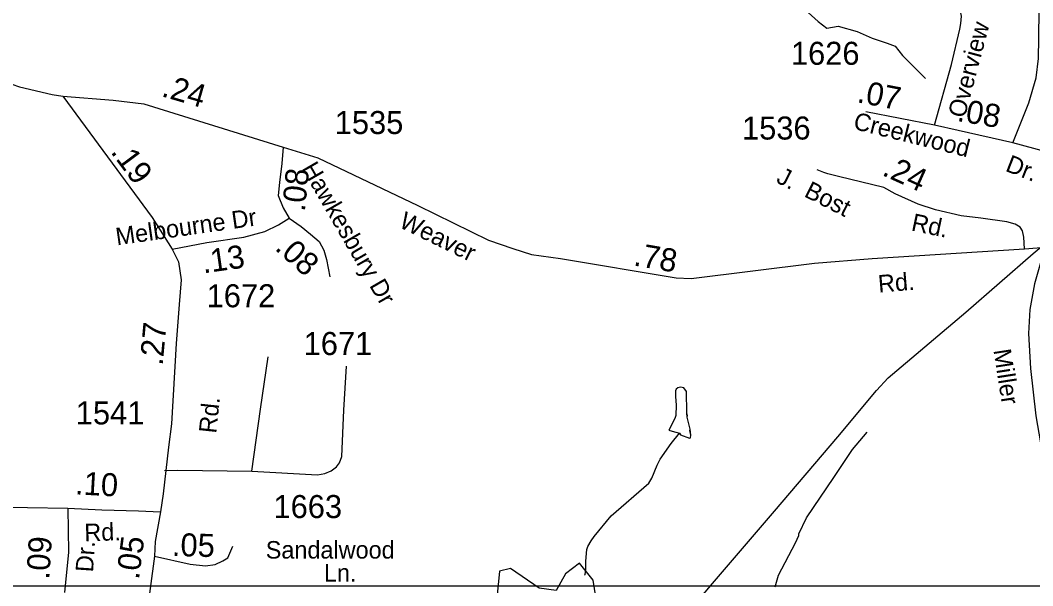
# Model space of a CAD drawing. Extents: x 1473865 to 1648260, y 639067 to 773536.
# Drawn here: x 1520569 to 1526062, y 678674 to 681743 of the extents above; entities that cross this region are included whole.
import ezdxf

# ---------------------------------------------------------------- set-up
doc = ezdxf.new("R2010")
doc.units = 0
for name, color, linetype in [('Exist Hydrographic Creek Single Shore', 7, 'Continuous'), ('Exist Hydrographic Misc Water Feature', 7, 'Continuous'), ('Exist Hydrographic Pond Under 1500 Sq Ft', 7, 'Continuous'), ('Exist Road Non-System Type 51', 7, 'Continuous'), ('Exist Road Secondary Mileage Hundredths English Label', 7, 'Continuous'), ('Exist Road Secondary Type 41 Attributed', 7, 'Continuous'), ('Exist Road Secondary Type 51 Attributed', 7, 'Continuous'), ('Exist Road Secondary Type 51 Label', 7, 'Continuous'), ('Exist Road Secondary Type 51 Number Label', 7, 'Continuous'), ('Exist Utilities Electrical Transmission Line', 7, 'Continuous'), ('Map Preparation Inset Cut Line', 7, 'Continuous')]:
    doc.layers.add(name, color=color, linetype=linetype)

msp = doc.modelspace()

# ---------------------------------------------------------------- linework, layer by layer
at = {"layer": 'Exist Hydrographic Creek Single Shore'}
msp.add_lwpolyline([(1524806.7, 681817.8), (1524897.3, 681736.4), (1524944.8, 681699.3), (1525006.6, 681709.8), (1525109, 681681.6), (1525190.1, 681645.1), (1525271.3, 681619.2), (1525316, 681602.7), (1525354.9, 681551), (1525480.7, 681426.7)], dxfattribs=at)
at = {"layer": 'Exist Hydrographic Misc Water Feature'}
for points in [[(1524145.9, 679501.4), (1524151.6, 679493.1), (1524199.5, 679474.1), (1524205.4, 679476.4), (1524207.6, 679492), (1524202, 679516.7), (1524204.2, 679524), (1524187.2, 679588.4), (1524189.2, 679596.5), (1524185.7, 679612.2), (1524183.5, 679728.8), (1524169.8, 679748.7), (1524151.7, 679751.6), (1524135.6, 679747.8), (1524127.5, 679741.4), (1524123.4, 679731.6), (1524123, 679701.3), (1524128.2, 679653.6), (1524125.3, 679597.8), (1524121, 679581.5), (1524088.2, 679518.2), (1524105.9, 679512.1), (1524145.9, 679501.4)], [(1524145.9, 679501.4), (1524151.6, 679493.1), (1524199.5, 679474.1), (1524205.4, 679476.4), (1524207.6, 679492), (1524204.2, 679524), (1524187.2, 679588.4), (1524185.7, 679612.2), (1524183.5, 679728.8), (1524169.8, 679748.7), (1524151.7, 679751.6), (1524135.6, 679747.8), (1524127.5, 679741.4), (1524123.4, 679731.6), (1524123, 679701.3), (1524128.2, 679653.6), (1524125.3, 679597.8), (1524121, 679581.5), (1524088.2, 679518.2), (1524105.9, 679512.1), (1524145.9, 679501.4)], [(1523629.6, 678730.6), (1523633.5, 678734.6), (1523637.9, 678759.2), (1523636.6, 678806.8), (1523643.6, 678870.6), (1523647.8, 678887), (1523666.4, 678918.6), (1523682.8, 678942.1), (1523774.5, 679052.6), (1523979.6, 679229.8), (1523995.9, 679257.4), (1524025, 679329), (1524041.5, 679360.7), (1524100.9, 679445.7), (1524145.9, 679501.4)], [(1524664.9, 678668.7), (1524682, 678732.3), (1524774.8, 678906.9), (1524793.4, 678946.7), (1524793.3, 678954.9), (1524835, 679041.9), (1524982.4, 679262.1), (1525084.9, 679412.7), (1525164.4, 679507.1)]]:
    msp.add_lwpolyline(points, dxfattribs=at)
at = {"layer": 'Exist Hydrographic Pond Under 1500 Sq Ft'}
msp.add_lwpolyline([(1523727.2, 678203.4), (1523779.1, 678300.9), (1523781.2, 678402.6), (1523707.2, 678512.4), (1523677.1, 678703.4), (1523603.1, 678796.8), (1523527.1, 678739.2), (1523476.2, 678648.4), (1523384.1, 678660.1), (1523228.2, 678768.2), (1523169.1, 678753.1), (1523150.1, 678569.6), (1523065.2, 678512.2), (1523056.1, 678463.2), (1523105.1, 678412.9), (1523379.2, 678299.1), (1523493.1, 678155.6), (1523559.1, 678121.5), (1523727.2, 678203.4)], dxfattribs=at)
at = {"layer": 'Exist Road Non-System Type 51'}
for points in [[(1521825.3, 679296), (1521872.6, 679631.6), (1521914.8, 679916.7)], [(1521825.3, 679296), (1522182.3, 679276.4), (1522221.4, 679282.6), (1522256.4, 679297), (1522285.2, 679319.6), (1522301.7, 679340.2), (1522314, 679375.2), (1522324.3, 679626.4), (1522338.7, 679865.2)], [(1521352, 679300.1), (1521424, 679302.1), (1521825.3, 679296)]]:
    msp.add_lwpolyline(points, dxfattribs=at)
at = {"layer": 'Exist Road Secondary Type 41 Attributed'}
msp.add_lwpolyline([(1526017.3, 680502.5), (1526013.8, 680564.9), (1526006.8, 680600.2), (1525993.8, 680619), (1525965.6, 680636.7), (1525920.9, 680649.6), (1525780.3, 680669.2), (1525673.4, 680681.8), (1525535.1, 680713.3), (1525440.8, 680744.7), (1525315.1, 680801.4), (1525254.9, 680835.5), (1525008.9, 680894.4), (1524950.1, 680908.5), (1524928.9, 680916.7), (1524891.9, 680931.2)], dxfattribs=at)
at = {"layer": 'Exist Road Secondary Type 51 Attributed'}
for p, q in [((1525528.2, 681173.3), (1525157.2, 681245.8)), ((1526017.3, 680502.5), (1526130.3, 680512))]:
    msp.add_line(p, q, dxfattribs=at)
for points in [[(1525953.8, 681077.9), (1526040.9, 681294.4), (1526079.7, 681429.8), (1526092.7, 681534.5), (1526095, 681645.1), (1526097.4, 681799.2), (1526083.2, 681939.3), (1526071.5, 682034.6), (1526058.5, 682108.7), (1526065.6, 682175.8), (1526095, 682432.3), (1526100.9, 682637), (1526100.9, 682706.5), (1526087.9, 682758.2), (1526062.1, 682807.7), (1526023.2, 682846.5), (1525991.5, 682878.3), (1525921.7, 682908.8), (1525870.2, 682922.6), (1525731.6, 682938.3), (1525558.4, 682921.4)], [(1525528.2, 681173.3), (1525620.5, 681502.2), (1525666.7, 681694.4), (1525672.6, 681726), (1525674.5, 681764.8), (1525667.9, 681801.6), (1525644.3, 681847.5), (1525614.9, 681881.6), (1525556.1, 681920.4), (1525455.9, 681954.8), (1525250.2, 682045.2), (1525186.6, 682081.6), (1525138.4, 682126.4), (1525117.2, 682173.4), (1525109, 682212.3), (1525099.5, 682400.5), (1525101, 682801.3)], [(1518591.3, 682427), (1518787.2, 682221.1), (1519092.2, 681892.2), (1519158, 681835.4), (1519202.8, 681805.4), (1519334.4, 681745.6), (1519695.9, 681629.7), (1519970.1, 681544.3), (1520314, 681467.5), (1520565.4, 681381.4), (1520741.5, 681339), (1520799.5, 681331.1)], [(1520799.5, 681331.1), (1521072.4, 681309.8), (1521239.9, 681289), (1521996.2, 681054)], [(1520799.5, 681331.1), (1521285.4, 680673.2), (1521393.4, 680501.3)], [(1525953.8, 681077.9), (1525657.4, 681143.8), (1525528.2, 681173.3)], [(1521996.2, 681054), (1521987.8, 680965.8), (1521975.7, 680862.1), (1521968.5, 680792.2), (1521995, 680724.7), (1522028.7, 680669.2)], [(1521996.2, 681054), (1522183.7, 680995.8), (1522726.7, 680737.3), (1523109, 680550.1), (1523242.1, 680503.4), (1523343.5, 680471.6), (1523499.1, 680450.6), (1524127.1, 680344.5), (1524209.1, 680340.8), (1524878.7, 680424), (1525191.1, 680450.1), (1526017.3, 680502.5)], [(1526344.5, 680934.4), (1526134.9, 681029.4), (1525953.8, 681077.9)], [(1521393.4, 680501.3), (1521580.5, 680536.5), (1521782.9, 680565.5), (1521896.2, 680596.8), (1521970.9, 680633), (1522028.7, 680669.2)], [(1522028.7, 680669.2), (1522093.8, 680623.4), (1522144.4, 680582.4), (1522190.2, 680541.4), (1522216.7, 680495.5), (1522231.1, 680444.9), (1522248, 680350.8)], [(1521393.4, 680501.3), (1521427.5, 680431.7), (1521442.3, 680333.8), (1521431.9, 680200.2), (1521415.6, 679988.1), (1521390.5, 679551.9), (1521374.1, 679426.8), (1521343.8, 679172.7), (1521329.9, 679075.4)], [(1526130.3, 680512), (1526106.8, 680439), (1526071.5, 680311.9), (1526046.8, 680173.1), (1526039.7, 680043.6), (1526050.4, 679853.1), (1526077.7, 679596), (1526128.8, 679302.5), (1526231.2, 678696.5), (1526259.3, 678619.4), (1526294.3, 678488.6), (1526335.8, 678351.4), (1526402.7, 678211.1), (1526496.5, 678073.8), (1526546.5, 677964.9), (1526603.5, 677869.8), (1526937.6, 677224.9), (1527173.3, 676812.1), (1527275.2, 676628.6), (1527383.7, 676412.1), (1527585.6, 676023.6), (1527618.7, 675951.5)], [(1517241.5, 676812), (1517600.6, 677026.9), (1518043.3, 677281.9), (1518428.4, 677507.3), (1518597.8, 677604.6), (1518714.1, 677675.4), (1518832.9, 677751.2), (1518932.7, 677822), (1519061.7, 677943.4), (1519261.4, 678151.9), (1519471.2, 678379.5), (1519668.4, 678601.9), (1519782.7, 678717.6), (1519891.4, 678835.2), (1519977.3, 678930), (1520034.2, 678981.8), (1520089.8, 679024.8), (1520189.5, 679072), (1520307.3, 679098.1), (1520445, 679101.9), (1520608.1, 679098.1), (1520828, 679094.3)], [(1520828, 679094.3), (1520830.6, 678856.7), (1520809.1, 678636.7)], [(1520828, 679094.3), (1521012.6, 679086.7), (1521211, 679080.7), (1521329.9, 679075.4)], [(1521329.9, 679075.4), (1521301.6, 678913.8), (1521297, 678835.2)], [(1521297, 678835.2), (1521490.4, 678791), (1521573.8, 678782.1), (1521625.7, 678788.4), (1521667.4, 678808.6), (1521695.2, 678826.3), (1521723, 678888.3)], [(1521297, 678835.2), (1521193.4, 678051.5), (1521158, 677773.4)]]:
    msp.add_lwpolyline(points, dxfattribs=at)
at = {"layer": 'Exist Utilities Electrical Transmission Line'}
msp.add_lwpolyline([(1523995.9, 678298.1), (1524324.1, 678686.3), (1524661, 679078.1), (1525004.1, 679482), (1525214.5, 679734.1), (1525277.7, 679803), (1525698.1, 680159.3), (1526063.7, 680476.7), (1526384.9, 680744), (1526581.4, 680943.3), (1527017.1, 681355.5), (1527413.7, 681732.3), (1528044.6, 682348.9), (1528386.4, 682674.8), (1528738.5, 683020.4), (1529088.6, 683369.9), (1529286.4, 683584.5), (1529759.7, 684112), (1530292.1, 684694.3), (1530813.9, 685256.9), (1531254.4, 685736.8), (1531515.5, 686026.1), (1531664.1, 686167.8)], dxfattribs=at)
at = {"layer": 'Map Preparation Inset Cut Line'}
msp.add_lwpolyline([(1530807.2, 690698.7), (1516075.6, 690698.7), (1516075.6, 678674.1), (1530807.2, 678674.1)], close=True, dxfattribs=at)

# ---------------------------------------------------------------- texts
at = {"layer": 'Exist Road Secondary Mileage Hundredths English Label'}
for s, rotation, p in [('.24', 343.7791, (1521330.5, 681331.4)), ('.07', 348.9491, (1525104.3, 681298.5)), ('.08', 350.3243, (1525646.9, 681196.6)), ('.19', 306.6499, (1521056.2, 681027.6)), ('.24', 335.7553, (1525239.1, 680904.1)), ('.08', 84.0991, (1522112.6, 680701.5)), ('.08', 318.1544, (1521945.6, 680500.9)), ('.13', 8.1373, (1521562.9, 680368.8)), ('.78', 350.4086, (1523892.1, 680412.3)), ('.27', 84.7514, (1521341.4, 679866.2)), ('.10', 356.7945, (1520864.4, 679170.5)), ('.05', 358.451, (1521390.7, 678835.6)), ('.09', 86.3353, (1520726.3, 678706)), ('.05', 82.5299, (1521212.9, 678704.4))]:
    msp.add_text(s, height=125, rotation=rotation, dxfattribs=at).set_placement(p)
at = {"layer": 'Exist Road Secondary Type 51 Label'}
for s, rotation, p in [('Overview', 75.1065, (1525692.1, 681207.5)), ('Creekwood', 346.0379, (1525083.4, 681153.7)), ('Dr.', 338.7159, (1525908.4, 680926.4)), ('Hawkesbury Dr', 300.0464, (1522092.9, 680939.4)), ('J.  Bost', 333.1971, (1524664.7, 680865)), ('Melbourne Dr', 8.1373, (1521093.6, 680520.6)), ('Weaver', 333.9047, (1522618, 680622.7)), ('Rd.', 348.1167, (1525398.3, 680602.6)), ('Rd.', 4.7768, (1525226.6, 680264.3)), ('Miller', 278.827, (1525848.3, 679952.4)), ('Rd.', 83.9116, (1521632.1, 679498.1)), ('Rd.', 1.8577, (1520918.2, 678914.8)), ('Dr.', 86.1712, (1520963.8, 678745.5))]:
    msp.add_text(s, height=95, rotation=rotation, dxfattribs=at).set_placement(p)
for s, p in [('Sandalwood', (1521901, 678821.4)), ('Ln.', (1522216.5, 678696.4))]:
    msp.add_text(s, height=95, dxfattribs=at).set_placement(p)
at = {"layer": 'Exist Road Secondary Type 51 Number Label'}
for s, p in [('1626', (1524750.2, 681500.9)), ('1535', (1522275.4, 681125.2)), ('1536', (1524484.9, 681095.3)), ('1672', (1521580.4, 680185.1)), ('1671', (1522106.7, 679926)), ('1541', (1520870.5, 679549.5)), ('1663', (1521943.1, 679041.3))]:
    msp.add_text(s, height=125, dxfattribs=at).set_placement(p)

doc.saveas('drawing.dxf')
